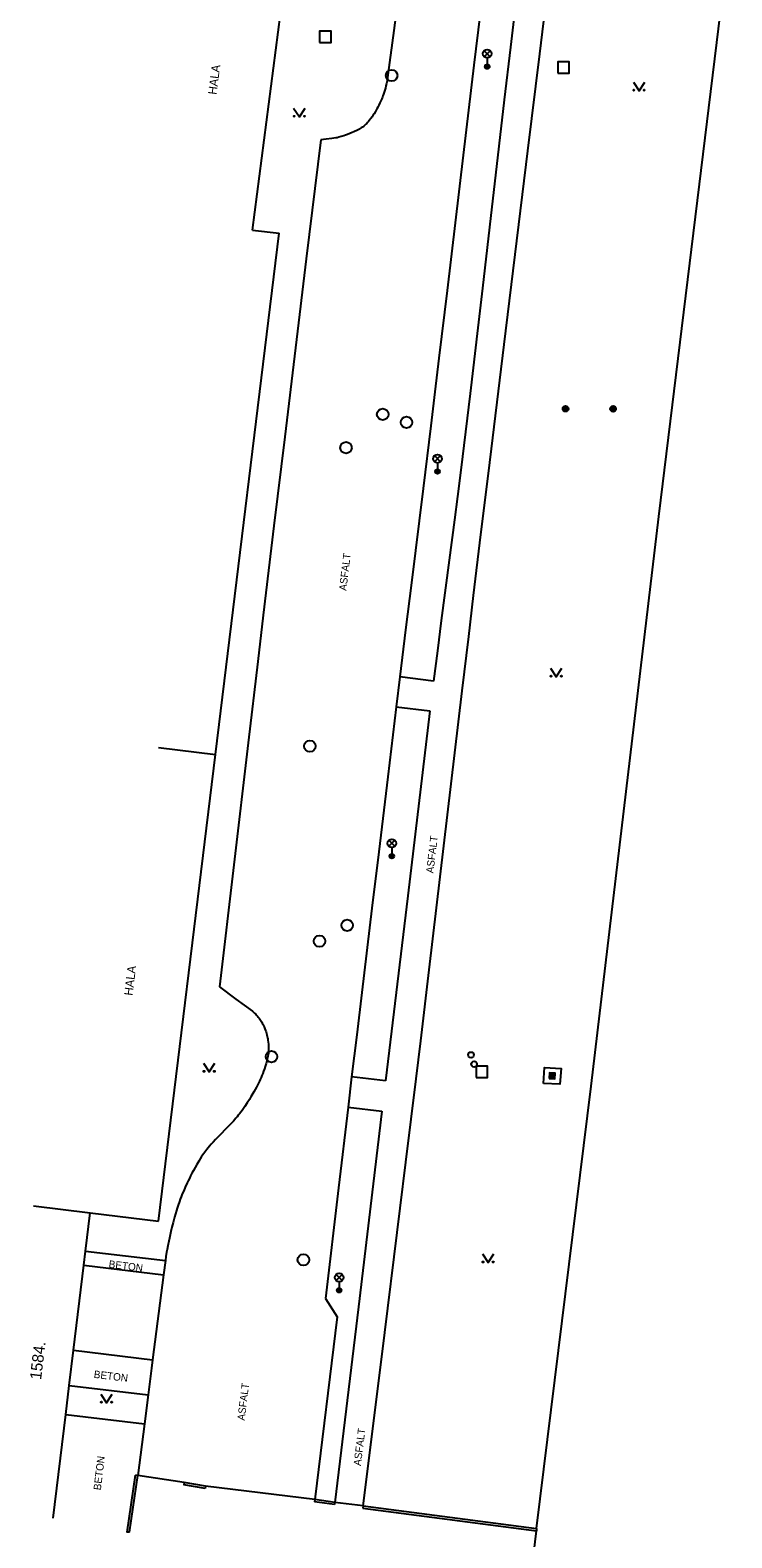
# Model space of a CAD drawing. Extents: x -541281 to -539153, y -1183881 to -1182141.
# Drawn here: x -540058.9 to -539997.7, y -1183453 to -1183321.5 of the extents above; entities that cross this region are included whole.
import ezdxf

# ---------------------------------------------------------------- set-up
doc = ezdxf.new("R2010")
doc.units = 0
for name, color, linetype in [('Vrstva 10', 7, 'Continuous'), ('Vrstva 11', 7, 'Continuous'), ('Vrstva 25', 7, 'Continuous'), ('Vrstva 26', 7, 'Continuous'), ('Vrstva 27', 7, 'Continuous'), ('Vrstva 28', 7, 'Continuous'), ('Vrstva 33', 7, 'Continuous'), ('Vrstva 36', 7, 'Continuous'), ('Vrstva 40', 7, 'Continuous'), ('Vrstva 41', 7, 'Continuous'), ('Vrstva 47', 7, 'Continuous'), ('Vrstva 5', 7, 'Continuous'), ('Vrstva 7', 7, 'Continuous'), ('Vrstva 8', 7, 'Continuous')]:
    doc.layers.add(name, color=color, linetype=linetype)

msp = doc.modelspace()

# ---------------------------------------------------------------- linework, layer by layer
at = {"layer": 'Vrstva 10'}
for p, q in [((-540019.64, -1183320.04), (-540020.18, -1183324.53)), ((-540020.18, -1183324.53), (-540021.12, -1183332.4)), ((-540033.55, -1183331.06), (-540034.81, -1183341.43)), ((-540021.12, -1183332.4), (-540022.53, -1183344.21)), ((-540034.81, -1183341.43), (-540036.69, -1183356.98)), ((-540022.53, -1183344.21), (-540023.24, -1183350.11)), ((-540023.95, -1183356.01), (-540024.62, -1183361.49)), ((-540036.69, -1183356.98), (-540037.63, -1183364.75)), ((-540024.62, -1183361.49), (-540025.63, -1183369.7)), ((-540038.56, -1183372.53), (-540039.04, -1183376.58)), ((-540039.04, -1183376.58), (-540039.88, -1183383.68)), ((-540026.64, -1183377.92), (-540026.96, -1183380.52)), ((-540026.96, -1183380.52), (-540027.7, -1183386.64)), ((-540039.88, -1183383.68), (-540042.37, -1183404.96)), ((-540027.7, -1183386.64), (-540028.49, -1183393.19)), ((-540028.49, -1183393.19), (-540029.09, -1183398.09)), ((-540029.09, -1183398.09), (-540029.97, -1183405.46)), ((-540030.85, -1183412.82), (-540031.16, -1183415.45)), ((-540031.16, -1183415.45), (-540031.99, -1183422.49)), ((-540044.5, -1183420.73), (-540044.65, -1183420.98)), ((-540031.99, -1183422.49), (-540033.14, -1183432.16)), ((-540047.1, -1183428.85), (-540047.26, -1183430.1)), ((-540047.26, -1183430.1), (-540048.21, -1183437.5)), ((-540033.14, -1183432.16), (-540032.12, -1183433.74)), ((-540032.12, -1183433.74), (-540034.05, -1183449.69)), ((-540048.21, -1183437.5), (-540048.31, -1183438.23))]:
    msp.add_line(p, q, dxfattribs=at)
for points in [[(-540026.34, -1183315.1), (-540026.67, -1183317.67), (-540027.17, -1183321.53)], [(-540027.17, -1183321.53), (-540027.68, -1183325.39), (-540027.72, -1183325.66), (-540027.76, -1183325.9), (-540027.81, -1183326.13), (-540027.86, -1183326.34), (-540027.91, -1183326.54), (-540027.96, -1183326.73), (-540028.02, -1183326.9), (-540028.07, -1183327.06), (-540028.12, -1183327.21), (-540028.17, -1183327.35), (-540028.23, -1183327.48)], [(-540028.23, -1183327.48), (-540028.28, -1183327.6), (-540028.38, -1183327.83), (-540028.47, -1183328.03), (-540028.56, -1183328.2), (-540028.64, -1183328.35), (-540028.71, -1183328.48), (-540028.78, -1183328.59), (-540028.9, -1183328.79), (-540029, -1183328.94), (-540029.07, -1183329.04), (-540029.19, -1183329.21), (-540029.31, -1183329.37), (-540029.39, -1183329.47), (-540029.46, -1183329.55), (-540029.53, -1183329.63), (-540029.6, -1183329.7), (-540029.67, -1183329.76)], [(-540029.67, -1183329.76), (-540029.73, -1183329.81), (-540029.79, -1183329.86), (-540029.9, -1183329.95), (-540030.01, -1183330.02), (-540030.1, -1183330.08), (-540030.18, -1183330.13), (-540030.33, -1183330.22), (-540030.45, -1183330.27), (-540030.53, -1183330.31), (-540030.67, -1183330.37), (-540030.8, -1183330.43), (-540031.02, -1183330.52), (-540031.21, -1183330.59), (-540031.38, -1183330.65), (-540031.53, -1183330.7), (-540031.66, -1183330.74), (-540031.77, -1183330.78), (-540031.97, -1183330.83), (-540032.12, -1183330.87), (-540032.23, -1183330.89), (-540032.4, -1183330.92), (-540032.57, -1183330.95), (-540033.06, -1183331), (-540033.55, -1183331.06)], [(-540023.24, -1183350.11), (-540023.59, -1183353.06), (-540023.95, -1183356.01)], [(-540037.63, -1183364.75), (-540038.1, -1183368.64), (-540038.56, -1183372.53)], [(-540025.63, -1183369.7), (-540026.14, -1183373.81), (-540026.64, -1183377.92)], [(-540042.37, -1183404.96), (-540040.94, -1183406.03), (-540039.51, -1183407.09), (-540039.41, -1183407.17), (-540039.31, -1183407.25), (-540039.22, -1183407.34), (-540039.14, -1183407.43), (-540039.06, -1183407.51), (-540038.99, -1183407.6), (-540038.92, -1183407.69), (-540038.86, -1183407.78), (-540038.8, -1183407.87), (-540038.74, -1183407.95), (-540038.69, -1183408.04), (-540038.65, -1183408.13), (-540038.6, -1183408.21), (-540038.56, -1183408.29), (-540038.48, -1183408.46), (-540038.42, -1183408.61), (-540038.36, -1183408.76), (-540038.32, -1183408.9), (-540038.28, -1183409.04), (-540038.24, -1183409.16), (-540038.21, -1183409.28), (-540038.19, -1183409.4), (-540038.17, -1183409.5), (-540038.15, -1183409.6), (-540038.12, -1183409.78), (-540038.11, -1183409.95), (-540038.1, -1183410.08), (-540038.09, -1183410.21), (-540038.09, -1183410.31), (-540038.09, -1183410.4), (-540038.1, -1183410.56), (-540038.1, -1183410.68), (-540038.11, -1183410.76), (-540038.13, -1183410.89), (-540038.15, -1183411.01), (-540038.18, -1183411.15), (-540038.21, -1183411.28), (-540038.24, -1183411.42), (-540038.27, -1183411.54), (-540038.31, -1183411.66), (-540038.38, -1183411.9), (-540038.45, -1183412.12), (-540038.53, -1183412.33), (-540038.6, -1183412.53), (-540038.68, -1183412.71), (-540038.75, -1183412.88)], [(-540029.97, -1183405.46), (-540030.41, -1183409.14), (-540030.85, -1183412.82)], [(-540038.75, -1183412.88), (-540038.82, -1183413.04), (-540038.89, -1183413.19), (-540039.03, -1183413.47), (-540039.15, -1183413.72), (-540039.27, -1183413.93), (-540039.37, -1183414.12), (-540039.46, -1183414.28), (-540039.63, -1183414.57), (-540039.76, -1183414.78), (-540039.96, -1183415.09), (-540040.17, -1183415.41), (-540040.29, -1183415.58), (-540040.4, -1183415.74), (-540040.51, -1183415.89), (-540040.63, -1183416.03), (-540040.74, -1183416.17), (-540040.84, -1183416.3), (-540040.95, -1183416.43), (-540041.16, -1183416.67), (-540041.36, -1183416.88), (-540041.55, -1183417.08), (-540041.9, -1183417.45), (-540042.21, -1183417.77), (-540042.48, -1183418.05), (-540042.72, -1183418.29), (-540042.92, -1183418.51), (-540043.09, -1183418.7), (-540043.24, -1183418.87), (-540043.37, -1183419.02), (-540043.48, -1183419.16), (-540043.57, -1183419.27), (-540043.73, -1183419.49), (-540043.85, -1183419.65), (-540043.94, -1183419.77), (-540044.06, -1183419.96), (-540044.18, -1183420.16), (-540044.35, -1183420.45), (-540044.5, -1183420.73)], [(-540044.65, -1183420.98), (-540044.78, -1183421.23), (-540044.9, -1183421.46), (-540045, -1183421.67), (-540045.1, -1183421.88), (-540045.2, -1183422.07), (-540045.36, -1183422.43), (-540045.5, -1183422.75), (-540045.62, -1183423.03), (-540045.72, -1183423.28), (-540045.81, -1183423.49), (-540045.88, -1183423.69), (-540045.99, -1183424.02), (-540046.08, -1183424.28)], [(-540046.08, -1183424.28), (-540046.14, -1183424.47), (-540046.22, -1183424.76), (-540046.3, -1183425.05), (-540046.42, -1183425.52), (-540046.53, -1183425.94), (-540046.61, -1183426.3), (-540046.69, -1183426.61), (-540046.75, -1183426.89), (-540046.8, -1183427.14), (-540046.89, -1183427.56), (-540046.95, -1183427.88), (-540046.99, -1183428.12), (-540047.05, -1183428.49), (-540047.1, -1183428.85)], [(-540048.31, -1183438.23), (-540048.61, -1183440.57), (-540048.93, -1183443.09), (-540049.51, -1183447.61)]]:
    msp.add_lwpolyline(points, dxfattribs=at)
at = {"layer": 'Vrstva 11'}
for p, q in [((-540014.43, -1183323.56), (-540013.4, -1183315.11)), ((-540015.47, -1183332.01), (-540014.43, -1183323.56)), ((-540018.01, -1183331.61), (-540018.83, -1183338.69)), ((-540017.54, -1183348.91), (-540015.47, -1183332.01)), ((-540018.83, -1183338.69), (-540019.44, -1183343.99)), ((-540018.92, -1183360.17), (-540017.54, -1183348.91)), ((-540019.57, -1183365.5), (-540018.92, -1183360.17)), ((-540021.63, -1183362.19), (-540021.89, -1183364.2)), ((-540021.89, -1183364.2), (-540022.34, -1183367.72)), ((-540020.21, -1183370.83), (-540019.57, -1183365.5)), ((-540022.34, -1183367.72), (-540023.03, -1183373)), ((-540023.7, -1183378.29), (-540026.64, -1183377.92)), ((-540023.44, -1183398.08), (-540021.2, -1183379.12)), ((-540026.96, -1183380.52), (-540024.02, -1183380.88)), ((-540024.02, -1183380.88), (-540025.96, -1183397.03)), ((-540025.96, -1183397.03), (-540027.9, -1183413.17)), ((-540024.09, -1183403.49), (-540023.44, -1183398.08)), ((-540024.83, -1183409.68), (-540024.09, -1183403.49)), ((-540027.9, -1183413.17), (-540030.85, -1183412.82)), ((-540031.16, -1183415.45), (-540028.21, -1183415.8)), ((-540028.21, -1183415.8), (-540030.26, -1183432.87)), ((-540028.22, -1183437.25), (-540026.61, -1183424.26)), ((-540054.05, -1183428.01), (-540047.1, -1183428.85)), ((-540054.2, -1183429.25), (-540047.26, -1183430.1)), ((-540030.26, -1183432.87), (-540032.31, -1183449.94)), ((-540055.1, -1183436.67), (-540048.21, -1183437.5)), ((-540029.84, -1183450.24), (-540028.22, -1183437.25)), ((-540055.48, -1183439.73), (-540048.61, -1183440.57)), ((-540055.78, -1183442.26), (-540048.93, -1183443.09))]:
    msp.add_line(p, q, dxfattribs=at)
for points in [[(-540016.05, -1183315.07), (-540016.39, -1183317.87), (-540016.71, -1183320.5), (-540017, -1183322.96)], [(-540017, -1183322.96), (-540017.54, -1183327.57), (-540018.01, -1183331.61)], [(-540019.44, -1183343.99), (-540019.91, -1183347.97), (-540020.26, -1183350.95), (-540020.52, -1183353.18)], [(-540020.52, -1183353.18), (-540020.93, -1183356.54), (-540021.34, -1183359.89), (-540021.63, -1183362.19)], [(-540021.2, -1183379.12), (-540020.63, -1183374.38), (-540020.21, -1183370.83)], [(-540023.03, -1183373), (-540023.37, -1183375.64), (-540023.7, -1183378.29)], [(-540025.66, -1183416.5), (-540025.23, -1183412.98), (-540024.83, -1183409.68)], [(-540026.61, -1183424.26), (-540026.11, -1183420.26), (-540025.66, -1183416.5)]]:
    msp.add_lwpolyline(points, dxfattribs=at)
at = {"layer": 'Vrstva 25'}
for points in [[(-540013.62, -1183412.96), (-540013.12, -1183413), (-540013.09, -1183412.5), (-540013.59, -1183412.46)], [(-540013.57, -1183412.92), (-540013.17, -1183412.94), (-540013.14, -1183412.54), (-540013.54, -1183412.52)], [(-540013.51, -1183412.87), (-540013.22, -1183412.89), (-540013.2, -1183412.59), (-540013.49, -1183412.57)], [(-540013.46, -1183412.82), (-540013.26, -1183412.84), (-540013.25, -1183412.64), (-540013.45, -1183412.62)], [(-540013.41, -1183412.78), (-540013.31, -1183412.78), (-540013.3, -1183412.68), (-540013.4, -1183412.68)]]:
    msp.add_lwpolyline(points, close=True, dxfattribs=at)
for centre, radius in [((-540012.19, -1183354.52), 0.25), ((-540012.19, -1183354.52), 0.2), ((-540012.19, -1183354.52), 0.15), ((-540012.19, -1183354.52), 0.1), ((-540012.19, -1183354.52), 0.05), ((-540008.05, -1183354.53), 0.25), ((-540008.05, -1183354.53), 0.2), ((-540008.05, -1183354.53), 0.15), ((-540008.05, -1183354.53), 0.1), ((-540008.05, -1183354.53), 0.05)]:
    msp.add_circle(centre, radius, dxfattribs=at)
at = {"layer": 'Vrstva 26'}
for points in [[(-540033.65, -1183322.57), (-540032.65, -1183322.57), (-540032.65, -1183321.57), (-540033.65, -1183321.57)], [(-540012.87, -1183325.24), (-540011.87, -1183325.24), (-540011.87, -1183324.24), (-540012.87, -1183324.24)], [(-540020, -1183412.88), (-540019, -1183412.88), (-540019, -1183411.88), (-540020, -1183411.88)]]:
    msp.add_lwpolyline(points, close=True, dxfattribs=at)
at = {"layer": 'Vrstva 27'}
for centre in [(-540027.36, -1183325.44), (-540028.14, -1183355.01), (-540026.07, -1183355.71), (-540031.34, -1183357.92), (-540034.49, -1183383.96), (-540031.24, -1183399.59), (-540033.65, -1183400.98), (-540037.84, -1183411.05), (-540035.06, -1183428.78)]:
    msp.add_circle(centre, 0.5, dxfattribs=at)
at = {"layer": 'Vrstva 28'}
for centre in [(-540020.44, -1183410.9), (-540020.17, -1183411.71)]:
    msp.add_circle(centre, 0.25, dxfattribs=at)
at = {"layer": 'Vrstva 33'}
for p, q in [((-540019.29, -1183323.81), (-540018.76, -1183323.28)), ((-540019.29, -1183323.28), (-540018.76, -1183323.81)), ((-540019.02, -1183323.92), (-540019.02, -1183324.67)), ((-540023.62, -1183359.14), (-540023.09, -1183358.61)), ((-540023.62, -1183358.61), (-540023.09, -1183359.14)), ((-540023.36, -1183359.25), (-540023.36, -1183360)), ((-540027.61, -1183392.7), (-540027.08, -1183392.17)), ((-540027.61, -1183392.17), (-540027.08, -1183392.7)), ((-540027.35, -1183392.81), (-540027.35, -1183393.56)), ((-540032.2, -1183430.58), (-540031.68, -1183430.05)), ((-540032.2, -1183430.05), (-540031.68, -1183430.58)), ((-540031.94, -1183430.69), (-540031.94, -1183431.44))]:
    msp.add_line(p, q, dxfattribs=at)
for centre, radius in [((-540019.02, -1183323.54), 0.375), ((-540019.02, -1183324.67), 0.2), ((-540019.02, -1183324.67), 0.145), ((-540019.02, -1183324.67), 0.0876), ((-540023.36, -1183358.88), 0.375), ((-540023.36, -1183360), 0.2), ((-540023.36, -1183360), 0.145), ((-540023.36, -1183360), 0.0876), ((-540027.35, -1183392.44), 0.375), ((-540027.35, -1183393.56), 0.2), ((-540027.35, -1183393.56), 0.145), ((-540027.35, -1183393.56), 0.0876), ((-540031.94, -1183430.31), 0.375), ((-540031.94, -1183431.44), 0.2), ((-540031.94, -1183431.44), 0.145), ((-540031.94, -1183431.44), 0.0876)]:
    msp.add_circle(centre, radius, dxfattribs=at)
at = {"layer": 'Vrstva 36'}
for points in [[(-540006.28, -1183326.02), (-540005.78, -1183326.77), (-540005.28, -1183326.02)], [(-540035.91, -1183328.3), (-540035.41, -1183329.05), (-540034.91, -1183328.3)], [(-540013.51, -1183377.16), (-540013.01, -1183377.91), (-540012.51, -1183377.16)], [(-540043.78, -1183411.63), (-540043.28, -1183412.38), (-540042.78, -1183411.63)], [(-540019.45, -1183428.27), (-540018.95, -1183429.02), (-540018.45, -1183428.27)], [(-540052.73, -1183440.5), (-540052.23, -1183441.25), (-540051.73, -1183440.5)]]:
    msp.add_lwpolyline(points, dxfattribs=at)
for centre in [(-540006.23, -1183326.72), (-540005.33, -1183326.72), (-540035.86, -1183329), (-540034.96, -1183329), (-540013.46, -1183377.86), (-540012.56, -1183377.86), (-540043.73, -1183412.33), (-540042.83, -1183412.33), (-540019.4, -1183428.97), (-540018.51, -1183428.97), (-540052.68, -1183441.2), (-540051.78, -1183441.2)]:
    msp.add_circle(centre, 0.05, dxfattribs=at)
at = {"layer": 'Vrstva 5'}
for p, q in [((-540039.51, -1183338.93), (-540036.26, -1183314.02)), ((-540042.74, -1183384.68), (-540037.18, -1183339.21)), ((-540039.51, -1183338.93), (-540037.18, -1183339.21)), ((-540047.7, -1183384.08), (-540042.74, -1183384.68)), ((-540047.69, -1183425.4), (-540042.74, -1183384.68)), ((-540058.61, -1183424.07), (-540053.65, -1183424.68)), ((-540054.05, -1183428.01), (-540053.65, -1183424.68)), ((-540053.65, -1183424.68), (-540047.69, -1183425.4)), ((-540054.2, -1183429.25), (-540054.05, -1183428.01)), ((-540055.1, -1183436.67), (-540054.2, -1183429.25)), ((-540055.48, -1183439.73), (-540055.1, -1183436.67)), ((-540055.78, -1183442.26), (-540055.48, -1183439.73)), ((-540056.89, -1183451.32), (-540055.78, -1183442.26))]:
    msp.add_line(p, q, dxfattribs=at)
at = {"layer": 'Vrstva 7'}
for p, q in [((-540004.06, -1183363.91), (-539997.69, -1183311.98)), ((-540009.97, -1183413.64), (-540004.06, -1183363.91)), ((-540014.72, -1183452.23), (-540009.97, -1183413.64)), ((-540050.24, -1183452.55), (-540049.51, -1183447.61)), ((-540049.51, -1183447.61), (-540049.71, -1183447.58)), ((-540045.46, -1183448.21), (-540045.49, -1183448.41)), ((-540043.64, -1183448.73), (-540045.49, -1183448.41)), ((-540043.61, -1183448.53), (-540045.46, -1183448.21)), ((-540043.61, -1183448.53), (-540043.64, -1183448.73)), ((-540034.05, -1183449.69), (-540034.08, -1183449.89)), ((-540032.34, -1183450.14), (-540034.08, -1183449.89)), ((-540032.31, -1183449.94), (-540034.05, -1183449.69)), ((-540032.31, -1183449.94), (-540032.34, -1183450.14)), ((-540029.84, -1183450.24), (-540029.87, -1183450.44)), ((-540029.87, -1183450.44), (-540014.74, -1183452.43)), ((-540017.76, -1183477.94), (-540014.74, -1183452.43))]:
    msp.add_line(p, q, dxfattribs=at)
for points in [[(-540014.13, -1183413.38), (-540014.03, -1183412.01), (-540012.58, -1183412.08), (-540012.68, -1183413.45), (-540014.13, -1183413.38)], [(-540050.24, -1183452.55), (-540050.44, -1183452.53), (-540049.71, -1183447.58)], [(-540029.84, -1183450.24), (-540014.72, -1183452.23), (-540014.74, -1183452.43)]]:
    msp.add_lwpolyline(points, dxfattribs=at)
at = {"layer": 'Vrstva 8'}
for p, q in [((-540045.46, -1183448.21), (-540049.51, -1183447.61)), ((-540034.05, -1183449.69), (-540043.61, -1183448.53)), ((-540029.84, -1183450.24), (-540032.31, -1183449.94))]:
    msp.add_line(p, q, dxfattribs=at)

# ---------------------------------------------------------------- texts
at = {"layer": 'Vrstva 40'}
for s, rotation, p in [('ASFALT', 82.9738, (-540031.32, -1183370.43)), ('ASFALT', 83.2452, (-540023.72, -1183395.08)), ('BETON', 353.0681, (-540052.07, -1183429.46)), ('BETON', 353.0691, (-540053.37, -1183439.07)), ('ASFALT', 83.1006, (-540040.18, -1183442.83)), ('ASFALT', 82.913, (-540030.05, -1183446.78)), ('BETON', 83.0693, (-540052.73, -1183448.91))]:
    msp.add_text(s, height=0.65, rotation=rotation, dxfattribs=at).set_placement(p)
at = {"layer": 'Vrstva 41'}
for rotation, p in [(82.5594, (-540042.64, -1183327.15)), (83.069, (-540049.96, -1183405.76))]:
    msp.add_text('HALA', height=0.75, rotation=rotation, dxfattribs=at).set_placement(p)
at = {"layer": 'Vrstva 47'}
msp.add_text('1584.', height=1, rotation=83.0693, dxfattribs=at).set_placement((-540057.94, -1183439.28))

doc.saveas('drawing.dxf')
